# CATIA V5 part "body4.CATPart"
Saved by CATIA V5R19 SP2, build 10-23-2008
Part number: body4
Bounding box of the stored display mesh (mm): x -1376.005 to 1941.021, y -716.33 to 716.33, z 5.338 to 556.099
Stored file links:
  C:\BEHROOZ\catia learning\tarh haye mashin\hb\body4.CATPart
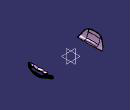
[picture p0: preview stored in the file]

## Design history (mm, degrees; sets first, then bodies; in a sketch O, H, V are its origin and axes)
Body1 (main body)
  Set1
    DatumSurface1
    DatumSurface2
    ThickSurface1: Surface DatumSurface2, TopOffset 0.1, BotOffset 0.1
    DatumSurface3
    ThickSurface2: Surface DatumSurface3, TopOffset 0.1, BotOffset 0.1
    DatumSurface4
    ThickSurface3: Surface DatumSurface4, TopOffset 0.1, BotOffset 0.1
    DatumSurface5
    ThickSurface4: Surface DatumSurface5, TopOffset 0.1, BotOffset 0.1
    DatumSurface6
    ThickSurface5: Surface DatumSurface6, TopOffset 0.1, BotOffset 0.1
    DatumSurface7
    ThickSurface6: Surface DatumSurface7, TopOffset 0.1, BotOffset 0.1
    DatumSurface8
    ThickSurface7: Surface DatumSurface8, TopOffset 0.1, BotOffset 0.1
    DatumSurface9
    ThickSurface8: Surface DatumSurface9, TopOffset 0.1, BotOffset 0.1
    DatumSurface10
    ThickSurface9: Surface DatumSurface10, TopOffset 0.1, BotOffset 0.1
    DatumSurface11
    ThickSurface10: Surface DatumSurface11, TopOffset 0.1, BotOffset 0.1
    DatumSurface12
    ThickSurface11: Surface DatumSurface12, TopOffset 0.1, BotOffset 0.1
    DatumSurface13
    ThickSurface12: Surface DatumSurface13, TopOffset 0.1, BotOffset 0.1
    DatumSurface14
    ThickSurface13: Surface DatumSurface14, TopOffset 0.1, BotOffset 0.1
    DatumSurface15
    ThickSurface14: Surface DatumSurface15, TopOffset 0.1, BotOffset 0.1
    DatumSurface16
    ThickSurface15: Surface DatumSurface16, TopOffset 0.1, BotOffset 0.1
    DatumSurface17
    ThickSurface16: Surface DatumSurface17, TopOffset 0.1, BotOffset 0.1
    DatumSurface18
    ThickSurface17: Surface DatumSurface18, TopOffset 0.1, BotOffset 0.1
    DatumSurface19
    ThickSurface18: Surface DatumSurface19, TopOffset 0.1, BotOffset 0.1
    DatumSurface20
    ThickSurface19: Surface DatumSurface20, TopOffset 0.1, BotOffset 0.1
    DatumSurface21
    ThickSurface20: Surface DatumSurface21, TopOffset 0.1, BotOffset 0.1
    DatumSurface22
    ThickSurface21: Surface DatumSurface22, TopOffset 0.1, BotOffset 0.1
    DatumSurface23
    DatumSurface24
    ThickSurface22: Surface DatumSurface23, TopOffset 0.1, BotOffset 0.1
    DatumSurface25 to DatumSurface32
    ThickSurface23: Surface DatumSurface28, TopOffset 0.1, BotOffset 0.1
    ThickSurface24: Surface DatumSurface27, TopOffset 0.1, BotOffset 0.1
    ThickSurface25: Surface DatumSurface26, TopOffset 0.1, BotOffset 0.1
    ThickSurface26: Surface DatumSurface25, TopOffset 0.1, BotOffset 0.1
    ThickSurface27: Surface DatumSurface30, TopOffset 0.1, BotOffset 0.1
    DatumSurface33
    ThickSurface28: Surface DatumSurface29, TopOffset 0.1, BotOffset 0.1
    DatumSurface34
    DatumSurface35
    ThickSurface29: Surface DatumSurface34, TopOffset 0.1, BotOffset 0.1
    ThickSurface30: Surface DatumSurface35, TopOffset 0.1, BotOffset 0.1
    DatumSurface36
    ThickSurface31: Surface DatumSurface36, TopOffset 1, BotOffset 0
